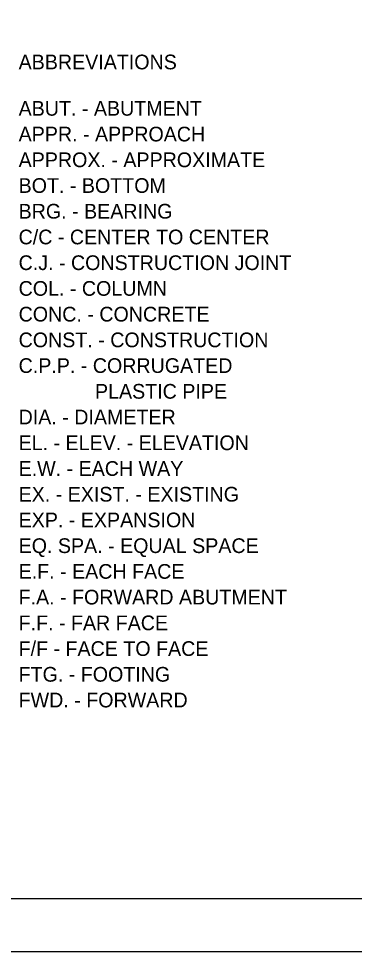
# Model space of a CAD drawing. Extents: x 0 to 34, y 0 to 22.
# Drawn here: x 24.66 to 27.86, y 0 to 8.88 of the extents above; entities that cross this region are included whole.
import ezdxf

# ---------------------------------------------------------------- set-up
doc = ezdxf.new("R2010")
doc.units = 0
for name, color, linetype in [('SH_Border', 7, 'Continuous'), ('SH_Cut_Line', 7, 'Continuous'), ('SH_Text', 7, 'Continuous')]:
    doc.layers.add(name, color=color, linetype=linetype)

msp = doc.modelspace()

# ---------------------------------------------------------------- linework, layer by layer
at = {"layer": 'SH_Border'}
msp.add_lwpolyline([(1.5, 21.5), (33.5, 21.5), (33.5, 0.5), (1.5, 0.5)], close=True, dxfattribs=at)
at = {"layer": 'SH_Cut_Line'}
msp.add_lwpolyline([(0, 0), (34, 0), (34, 22), (0, 22)], close=True, dxfattribs=at)

# ---------------------------------------------------------------- texts
at = {"layer": 'SH_Text'}
for s, p in [('ABBREVIATIONS', (24.66, 8.4)), ('ABUT. - ABUTMENT', (24.66, 7.9584)), ('APPR. - APPROACH', (24.66, 7.7134)), ('APPROX. - APPROXIMATE', (24.66, 7.4684)), ('BOT. - BOTTOM', (24.66, 7.2234)), ('BRG. - BEARING', (24.66, 6.9784)), ('C/C - CENTER TO CENTER', (24.66, 6.7334)), ('C.J. - CONSTRUCTION JOINT', (24.66, 6.4884)), ('COL. - COLUMN', (24.66, 6.2434)), ('CONC. - CONCRETE', (24.66, 5.9984)), ('CONST. - CONSTRUCTION', (24.66, 5.7534)), ('C.P.P. - CORRUGATED ', (24.66, 5.5084)), ('              PLASTIC PIPE', (24.66, 5.2634)), ('DIA. - DIAMETER', (24.66, 5.0184)), ('EL. - ELEV. - ELEVATION', (24.66, 4.7734)), ('E.W. - EACH WAY', (24.66, 4.5284)), ('EX. - EXIST. - EXISTING', (24.66, 4.2834)), ('EXP. - EXPANSION', (24.66, 4.0384)), ('EQ. SPA. - EQUAL SPACE', (24.66, 3.7934)), ('E.F. - EACH FACE', (24.66, 3.5484)), ('F.A. - FORWARD ABUTMENT', (24.66, 3.3034)), ('F.F. - FAR FACE', (24.66, 3.0584)), ('F/F - FACE TO FACE', (24.66, 2.8134)), ('FTG. - FOOTING', (24.66, 2.5684)), ('FWD. - FORWARD', (24.66, 2.3234))]:
    msp.add_text(s, height=0.14, dxfattribs=at).set_placement(p)

doc.saveas('drawing.dxf')
